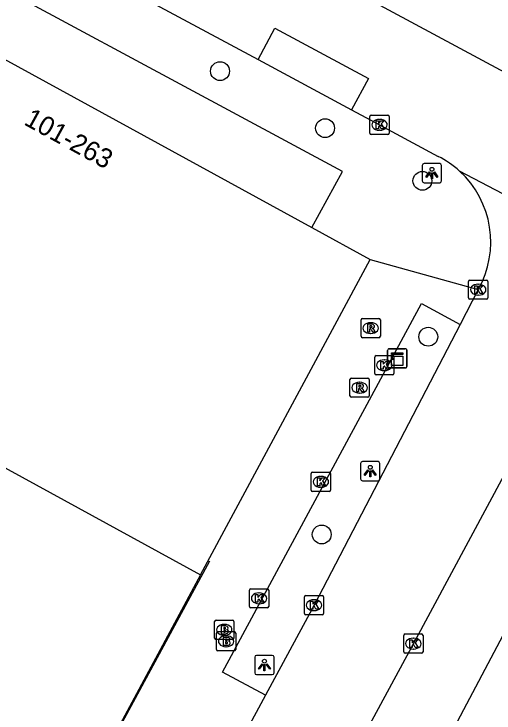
# Model space of a CAD drawing. Extents: x 159489 to 160304, y 383826 to 384530.
# Drawn here: x 159630.6 to 159655.5, y 384218.51 to 384254.79 of the extents above; entities that cross this region are included whole.
import ezdxf

# ---------------------------------------------------------------- set-up
doc = ezdxf.new("R2010")
doc.units = 0
for name, color, linetype in [('IMGEO_Boom', 7, 'Continuous'), ('IMGEO_Brandkraan', 7, 'Continuous'), ('IMGEO_Kast', 7, 'Continuous'), ('IMGEO_Kolk', 7, 'Continuous'), ('IMGEO_Lichtpunt', 7, 'Continuous'), ('IMGEO_Lijnafwatering', 7, 'Continuous'), ('IMGEO_Pand', 7, 'Continuous'), ('IMGEO_Pand_nummerreeks', 7, 'Continuous'), ('IMGEO_Pand_overbouw', 7, 'Continuous'), ('IMGEO_Rijbaan_lokaal_gesloten', 7, 'Continuous'), ('IMGEO_Rioolput', 7, 'Continuous'), ('IMGEO_Voetpad_open', 7, 'Continuous')]:
    doc.layers.add(name, color=color, linetype=linetype)

msp = doc.modelspace()

# ---------------------------------------------------------------- linework, layer by layer
at = {"layer": 'IMGEO_Boom'}
for centre in [(159641.29, 384251.824), (159646.74, 384248.864), (159651.788, 384246.131), (159652.093, 384238.04), (159646.565, 384227.78)]:
    msp.add_circle(centre, 0.489, dxfattribs=at)
at = {"layer": 'IMGEO_Brandkraan'}
for p, q in [((159641.085, 384223.33), (159641.937, 384223.33)), ((159641.01, 384222.404), (159641.01, 384223.256)), ((159641.498, 384223.11), (159641.523, 384223.11)), ((159642.011, 384223.256), (159642.011, 384222.404)), ((159641.105, 384221.81), (159641.105, 384222.662)), ((159641.18, 384222.736), (159642.032, 384222.736)), ((159642.106, 384222.662), (159642.106, 384221.81)), ((159641.937, 384222.33), (159641.085, 384222.33)), ((159641.521, 384222.55), (159641.496, 384222.55)), ((159641.593, 384222.516), (159641.618, 384222.516)), ((159641.616, 384221.956), (159641.591, 384221.956)), ((159642.032, 384221.736), (159641.18, 384221.736))]:
    msp.add_line(p, q, dxfattribs=at)
for points in [[(159641.085, 384223.33), (159641.937, 384223.33)], [(159641.01, 384222.404), (159641.01, 384223.256)], [(159641.358, 384223.03), (159641.358, 384222.63), (159641.571, 384222.63)], [(159641.589, 384223.03), (159641.358, 384223.03)], [(159641.537, 384222.949), (159641.483, 384222.949), (159641.483, 384222.873)], [(159642.011, 384223.256), (159642.011, 384222.404)], [(159641.105, 384221.81), (159641.105, 384222.662)], [(159641.18, 384222.736), (159642.032, 384222.736)], [(159641.483, 384222.873), (159641.536, 384222.873)], [(159641.545, 384222.797), (159641.483, 384222.797), (159641.483, 384222.716)], [(159641.483, 384222.716), (159641.545, 384222.716)], [(159642.106, 384222.662), (159642.106, 384221.81)], [(159641.937, 384222.33), (159641.085, 384222.33)], [(159641.453, 384222.436), (159641.453, 384222.036), (159641.666, 384222.036)], [(159641.684, 384222.436), (159641.453, 384222.436)], [(159641.632, 384222.355), (159641.578, 384222.355), (159641.578, 384222.279)], [(159641.578, 384222.279), (159641.631, 384222.279)], [(159641.64, 384222.203), (159641.578, 384222.203), (159641.578, 384222.122)], [(159641.578, 384222.122), (159641.64, 384222.122)], [(159642.032, 384221.736), (159641.18, 384221.736)]]:
    msp.add_lwpolyline(points, dxfattribs=at)
for centre, radius, start, end in [((159641.087, 384223.254), 0.0765, 91.552, 178.448), ((159641.087, 384223.254), 0.0765, 91.552, 178.448), ((159641.935, 384223.254), 0.0765, 1.552, 88.448), ((159641.935, 384223.254), 0.0765, 1.552, 88.448), ((159641.538, 384222.911), 0.0379, 267.8285, 90.9355), ((159641.593, 384222.885), 0.145, 59.4692, 91.5367), ((159641.618, 384222.932), 0.0922, 285.5137, 58.1501), ((159641.182, 384222.66), 0.0765, 91.552, 178.448), ((159641.182, 384222.66), 0.0765, 91.552, 178.448), ((159641.546, 384222.756), 0.0404, 269.8759, 90.5077), ((159641.577, 384222.881), 0.251, 268.6676, 293.5347), ((159641.623, 384222.74), 0.105, 301.3115, 78.989), ((159642.03, 384222.66), 0.0765, 1.552, 88.448), ((159642.03, 384222.66), 0.0765, 1.552, 88.448), ((159641.087, 384222.406), 0.0765, 181.552, 268.448), ((159641.087, 384222.406), 0.0765, 181.552, 268.448), ((159641.633, 384222.317), 0.0379, 267.8285, 90.9355), ((159641.641, 384222.162), 0.0404, 269.8759, 90.5077), ((159641.688, 384222.291), 0.145, 59.4692, 91.5367), ((159641.713, 384222.338), 0.0922, 285.5137, 58.1501), ((159641.718, 384222.146), 0.105, 301.3115, 78.989), ((159641.935, 384222.406), 0.0765, 271.552, 358.448), ((159641.935, 384222.406), 0.0765, 271.552, 358.448), ((159641.672, 384222.287), 0.251, 268.6676, 293.5347), ((159641.182, 384221.812), 0.0765, 181.552, 268.448), ((159641.182, 384221.812), 0.0765, 181.552, 268.448), ((159642.03, 384221.812), 0.0765, 271.552, 358.448), ((159642.03, 384221.812), 0.0765, 271.552, 358.448)]:
    msp.add_arc(centre, radius, start, end, dxfattribs=at)
for centre, major_axis, ratio, start_param, end_param in [((159641.497, 384222.83), (-0.387, 0.002), 0.722429, 4.712389, 7.853982), ((159641.522, 384222.83), (-0.39, 0.002), 0.717154, 1.570796, 4.712389), ((159641.592, 384222.236), (-0.387, 0.002), 0.722429, 4.712389, 7.853982), ((159641.617, 384222.236), (-0.39, 0.002), 0.717154, 1.570796, 4.712389)]:
    msp.add_ellipse(centre, major_axis=major_axis, ratio=ratio, start_param=start_param, end_param=end_param, dxfattribs=at)
at = {"layer": 'IMGEO_Kast'}
for p, q in [((159649.985, 384236.494), (159649.985, 384237.335)), ((159649.985, 384237.335), (159649.985, 384236.494)), ((159650.06, 384237.419), (159650.901, 384237.419)), ((159650.901, 384237.419), (159650.06, 384237.419)), ((159650.985, 384237.344), (159650.985, 384236.503)), ((159650.985, 384236.503), (159650.985, 384237.344)), ((159650.91, 384236.419), (159650.069, 384236.419)), ((159650.069, 384236.419), (159650.91, 384236.419))]:
    msp.add_line(p, q, dxfattribs=at)
for points in [[(159650.18, 384237.209), (159650.78, 384237.209), (159650.78, 384237.124), (159650.18, 384237.124), (159650.18, 384237.209)], [(159650.18, 384237.034), (159650.78, 384237.034), (159650.78, 384236.545), (159650.18, 384236.545), (159650.18, 384237.034)]]:
    msp.add_lwpolyline(points, dxfattribs=at)
msp.add_circle((159650.264, 384236.883), 0.0377, dxfattribs=at)
for centre, start, end in [((159650.063, 384237.341), 92.4484, 184.2845), ((159650.063, 384237.341), 92.4484, 184.2845), ((159650.907, 384237.341), 2.4484, 94.2845), ((159650.907, 384237.341), 2.4484, 94.2845), ((159650.063, 384236.497), 182.4484, 274.2845), ((159650.063, 384236.497), 182.4484, 274.2845), ((159650.907, 384236.497), 272.4484, 4.2845), ((159650.907, 384236.497), 272.4484, 4.2845)]:
    msp.add_arc(centre, 0.0779, start, end, dxfattribs=at)
at = {"layer": 'IMGEO_Kolk'}
for p, q in [((159649.064, 384248.611), (159649.064, 384249.463)), ((159649.139, 384249.537), (159649.991, 384249.537)), ((159650.065, 384249.463), (159650.065, 384248.611)), ((159649.552, 384249.317), (159649.577, 384249.317)), ((159649.575, 384248.757), (159649.55, 384248.757)), ((159649.991, 384248.537), (159649.139, 384248.537)), ((159654.183, 384240.058), (159654.183, 384240.91)), ((159654.258, 384240.984), (159655.11, 384240.984)), ((159654.671, 384240.764), (159654.696, 384240.764)), ((159655.184, 384240.91), (159655.184, 384240.058)), ((159655.11, 384239.984), (159654.258, 384239.984)), ((159654.694, 384240.204), (159654.669, 384240.204)), ((159649.313, 384236.135), (159649.313, 384236.987)), ((159649.388, 384237.061), (159650.24, 384237.061)), ((159649.801, 384236.841), (159649.826, 384236.841)), ((159650.314, 384236.987), (159650.314, 384236.135)), ((159650.24, 384236.061), (159649.388, 384236.061)), ((159649.824, 384236.281), (159649.799, 384236.281)), ((159646.021, 384230.086), (159646.021, 384230.938)), ((159646.096, 384231.012), (159646.948, 384231.012)), ((159647.022, 384230.938), (159647.022, 384230.086)), ((159646.509, 384230.792), (159646.534, 384230.792)), ((159646.532, 384230.232), (159646.507, 384230.232)), ((159646.948, 384230.012), (159646.096, 384230.012)), ((159642.816, 384224.039), (159642.816, 384224.891)), ((159642.891, 384224.965), (159643.743, 384224.965)), ((159643.304, 384224.745), (159643.329, 384224.745)), ((159643.817, 384224.891), (159643.817, 384224.039)), ((159645.665, 384223.684), (159645.665, 384224.536)), ((159645.74, 384224.61), (159646.592, 384224.61)), ((159646.153, 384224.39), (159646.178, 384224.39)), ((159646.666, 384224.536), (159646.666, 384223.684)), ((159643.327, 384224.185), (159643.302, 384224.185)), ((159643.743, 384223.965), (159642.891, 384223.965)), ((159646.176, 384223.83), (159646.151, 384223.83)), ((159646.592, 384223.61), (159645.74, 384223.61)), ((159650.895, 384222.615), (159651.747, 384222.615)), ((159650.82, 384221.689), (159650.82, 384222.541)), ((159651.308, 384222.395), (159651.333, 384222.395)), ((159651.821, 384222.541), (159651.821, 384221.689)), ((159651.747, 384221.615), (159650.895, 384221.615)), ((159651.331, 384221.835), (159651.306, 384221.835))]:
    msp.add_line(p, q, dxfattribs=at)
for points in [[(159649.064, 384248.611), (159649.064, 384249.463)], [(159649.139, 384249.537), (159649.991, 384249.537)], [(159650.065, 384249.463), (159650.065, 384248.611)], [(159649.385, 384249.237), (159649.508, 384249.237), (159649.508, 384249.086), (159649.638, 384249.237), (159649.802, 384249.237), (159649.656, 384249.086), (159649.809, 384248.837), (159649.657, 384248.837), (159649.572, 384249.001), (159649.508, 384248.934), (159649.508, 384248.837), (159649.385, 384248.837), (159649.385, 384249.237)], [(159649.991, 384248.537), (159649.139, 384248.537)], [(159654.183, 384240.058), (159654.183, 384240.91)], [(159654.258, 384240.984), (159655.11, 384240.984)], [(159655.184, 384240.91), (159655.184, 384240.058)], [(159654.504, 384240.684), (159654.627, 384240.684), (159654.627, 384240.533), (159654.757, 384240.684), (159654.921, 384240.684), (159654.775, 384240.533), (159654.928, 384240.284), (159654.776, 384240.284), (159654.691, 384240.448), (159654.627, 384240.381), (159654.627, 384240.284), (159654.504, 384240.284), (159654.504, 384240.684)], [(159655.11, 384239.984), (159654.258, 384239.984)], [(159649.313, 384236.135), (159649.313, 384236.987)], [(159649.388, 384237.061), (159650.24, 384237.061)], [(159649.634, 384236.761), (159649.757, 384236.761), (159649.757, 384236.61), (159649.887, 384236.761), (159650.051, 384236.761), (159649.905, 384236.61), (159650.058, 384236.361), (159649.906, 384236.361), (159649.821, 384236.525), (159649.757, 384236.458), (159649.757, 384236.361), (159649.634, 384236.361), (159649.634, 384236.761)], [(159650.314, 384236.987), (159650.314, 384236.135)], [(159650.24, 384236.061), (159649.388, 384236.061)], [(159646.021, 384230.086), (159646.021, 384230.938)], [(159646.096, 384231.012), (159646.948, 384231.012)], [(159647.022, 384230.938), (159647.022, 384230.086)], [(159646.342, 384230.712), (159646.465, 384230.712), (159646.465, 384230.561), (159646.595, 384230.712), (159646.759, 384230.712), (159646.613, 384230.561), (159646.766, 384230.312), (159646.614, 384230.312), (159646.529, 384230.476), (159646.465, 384230.409), (159646.465, 384230.312), (159646.342, 384230.312), (159646.342, 384230.712)], [(159646.948, 384230.012), (159646.096, 384230.012)], [(159642.816, 384224.039), (159642.816, 384224.891)], [(159642.891, 384224.965), (159643.743, 384224.965)], [(159643.817, 384224.891), (159643.817, 384224.039)], [(159643.137, 384224.665), (159643.26, 384224.665), (159643.26, 384224.514), (159643.39, 384224.665), (159643.554, 384224.665), (159643.408, 384224.514), (159643.561, 384224.265), (159643.409, 384224.265), (159643.324, 384224.429), (159643.26, 384224.362), (159643.26, 384224.265), (159643.137, 384224.265), (159643.137, 384224.665)], [(159645.665, 384223.684), (159645.665, 384224.536)], [(159645.74, 384224.61), (159646.592, 384224.61)], [(159646.666, 384224.536), (159646.666, 384223.684)], [(159645.986, 384224.31), (159646.109, 384224.31), (159646.109, 384224.159), (159646.239, 384224.31), (159646.403, 384224.31), (159646.257, 384224.159), (159646.41, 384223.91), (159646.258, 384223.91), (159646.173, 384224.074), (159646.109, 384224.007), (159646.109, 384223.91), (159645.986, 384223.91), (159645.986, 384224.31)], [(159643.743, 384223.965), (159642.891, 384223.965)], [(159646.592, 384223.61), (159645.74, 384223.61)], [(159650.895, 384222.615), (159651.747, 384222.615)], [(159650.82, 384221.689), (159650.82, 384222.541)], [(159651.141, 384222.315), (159651.264, 384222.315), (159651.264, 384222.164), (159651.394, 384222.315), (159651.558, 384222.315), (159651.412, 384222.164), (159651.565, 384221.915), (159651.413, 384221.915), (159651.328, 384222.079), (159651.264, 384222.012), (159651.264, 384221.915), (159651.141, 384221.915), (159651.141, 384222.315)], [(159651.821, 384222.541), (159651.821, 384221.689)], [(159651.747, 384221.615), (159650.895, 384221.615)]]:
    msp.add_lwpolyline(points, dxfattribs=at)
for centre, start, end in [((159649.141, 384249.461), 91.552, 178.448), ((159649.141, 384249.461), 91.552, 178.448), ((159649.989, 384249.461), 1.552, 88.448), ((159649.989, 384249.461), 1.552, 88.448), ((159649.141, 384248.613), 181.552, 268.448), ((159649.141, 384248.613), 181.552, 268.448), ((159649.989, 384248.613), 271.552, 358.448), ((159649.989, 384248.613), 271.552, 358.448), ((159654.26, 384240.908), 91.552, 178.448), ((159654.26, 384240.908), 91.552, 178.448), ((159655.108, 384240.908), 1.552, 88.448), ((159655.108, 384240.908), 1.552, 88.448), ((159654.26, 384240.06), 181.552, 268.448), ((159654.26, 384240.06), 181.552, 268.448), ((159655.108, 384240.06), 271.552, 358.448), ((159655.108, 384240.06), 271.552, 358.448), ((159649.39, 384236.985), 91.552, 178.448), ((159649.39, 384236.985), 91.552, 178.448), ((159650.238, 384236.985), 1.552, 88.448), ((159650.238, 384236.985), 1.552, 88.448), ((159649.39, 384236.137), 181.552, 268.448), ((159649.39, 384236.137), 181.552, 268.448), ((159650.238, 384236.137), 271.552, 358.448), ((159650.238, 384236.137), 271.552, 358.448), ((159646.098, 384230.936), 91.552, 178.448), ((159646.098, 384230.936), 91.552, 178.448), ((159646.946, 384230.936), 1.552, 88.448), ((159646.946, 384230.936), 1.552, 88.448), ((159646.098, 384230.088), 181.552, 268.448), ((159646.098, 384230.088), 181.552, 268.448), ((159646.946, 384230.088), 271.552, 358.448), ((159646.946, 384230.088), 271.552, 358.448), ((159642.893, 384224.889), 91.552, 178.448), ((159642.893, 384224.889), 91.552, 178.448), ((159643.741, 384224.889), 1.552, 88.448), ((159643.741, 384224.889), 1.552, 88.448), ((159645.742, 384224.534), 91.552, 178.448), ((159645.742, 384224.534), 91.552, 178.448), ((159646.59, 384224.534), 1.552, 88.448), ((159646.59, 384224.534), 1.552, 88.448), ((159642.893, 384224.041), 181.552, 268.448), ((159642.893, 384224.041), 181.552, 268.448), ((159643.741, 384224.041), 271.552, 358.448), ((159643.741, 384224.041), 271.552, 358.448), ((159645.742, 384223.686), 181.552, 268.448), ((159645.742, 384223.686), 181.552, 268.448), ((159646.59, 384223.686), 271.552, 358.448), ((159646.59, 384223.686), 271.552, 358.448), ((159650.897, 384222.539), 91.552, 178.448), ((159650.897, 384222.539), 91.552, 178.448), ((159651.745, 384222.539), 1.552, 88.448), ((159651.745, 384222.539), 1.552, 88.448), ((159650.897, 384221.691), 181.552, 268.448), ((159650.897, 384221.691), 181.552, 268.448), ((159651.745, 384221.691), 271.552, 358.448), ((159651.745, 384221.691), 271.552, 358.448)]:
    msp.add_arc(centre, 0.0765, start, end, dxfattribs=at)
for centre, major_axis, ratio, start_param, end_param in [((159649.551, 384249.037), (-0.387, 0.002), 0.722429, 4.712389, 7.853982), ((159649.576, 384249.037), (-0.39, 0.002), 0.717154, 1.570796, 4.712389), ((159654.67, 384240.484), (-0.387, 0.002), 0.722429, 4.712389, 7.853982), ((159654.695, 384240.484), (-0.39, 0.002), 0.717154, 1.570796, 4.712389), ((159649.8, 384236.561), (-0.387, 0.002), 0.722429, 4.712389, 7.853982), ((159649.825, 384236.561), (-0.39, 0.002), 0.717154, 1.570796, 4.712389), ((159646.508, 384230.512), (-0.387, 0.002), 0.722429, 4.712389, 7.853982), ((159646.533, 384230.512), (-0.39, 0.002), 0.717154, 1.570796, 4.712389), ((159643.303, 384224.465), (-0.387, 0.002), 0.722429, 4.712389, 7.853982), ((159643.328, 384224.465), (-0.39, 0.002), 0.717154, 1.570796, 4.712389), ((159646.152, 384224.11), (-0.387, 0.002), 0.722429, 4.712389, 7.853982), ((159646.177, 384224.11), (-0.39, 0.002), 0.717154, 1.570796, 4.712389), ((159651.307, 384222.115), (-0.387, 0.002), 0.722429, 4.712389, 7.853982), ((159651.332, 384222.115), (-0.39, 0.002), 0.717154, 1.570796, 4.712389)]:
    msp.add_ellipse(centre, major_axis=major_axis, ratio=ratio, start_param=start_param, end_param=end_param, dxfattribs=at)
at = {"layer": 'IMGEO_Lichtpunt'}
for p, q in [((159651.784, 384246.933), (159651.784, 384246.126)), ((159651.784, 384246.933), (159651.784, 384246.126)), ((159652.686, 384247.028), (159651.878, 384247.028)), ((159652.686, 384247.028), (159651.878, 384247.028)), ((159652.78, 384246.126), (159652.78, 384246.933)), ((159652.78, 384246.126), (159652.78, 384246.933)), ((159651.878, 384246.032), (159652.686, 384246.032)), ((159651.878, 384246.032), (159652.686, 384246.032)), ((159648.585, 384231.469), (159648.585, 384230.662)), ((159648.585, 384231.469), (159648.585, 384230.662)), ((159649.487, 384231.564), (159648.679, 384231.564)), ((159649.487, 384231.564), (159648.679, 384231.564)), ((159649.581, 384230.662), (159649.581, 384231.469)), ((159649.581, 384230.662), (159649.581, 384231.469)), ((159648.679, 384230.568), (159649.487, 384230.568)), ((159648.679, 384230.568), (159649.487, 384230.568)), ((159643.997, 384221.505), (159643.189, 384221.505)), ((159643.997, 384221.505), (159643.189, 384221.505)), ((159643.095, 384221.41), (159643.095, 384220.603)), ((159643.095, 384221.41), (159643.095, 384220.603)), ((159644.091, 384220.603), (159644.091, 384221.41)), ((159644.091, 384220.603), (159644.091, 384221.41)), ((159643.189, 384220.509), (159643.997, 384220.509)), ((159643.189, 384220.509), (159643.997, 384220.509))]:
    msp.add_line(p, q, dxfattribs=at)
for points in [[(159652.158, 384246.597), (159652.197, 384246.569), (159652.009, 384246.307), (159651.971, 384246.334), (159652.158, 384246.597)], [(159652.26, 384246.549), (159652.307, 384246.549), (159652.307, 384246.227), (159652.26, 384246.227), (159652.26, 384246.549)], [(159652.37, 384246.569), (159652.408, 384246.596), (159652.595, 384246.334), (159652.556, 384246.306), (159652.37, 384246.569)], [(159648.959, 384231.133), (159648.998, 384231.105), (159648.81, 384230.843), (159648.772, 384230.87), (159648.959, 384231.133)], [(159649.061, 384231.085), (159649.108, 384231.085), (159649.108, 384230.763), (159649.061, 384230.763), (159649.061, 384231.085)], [(159649.171, 384231.105), (159649.209, 384231.132), (159649.396, 384230.87), (159649.357, 384230.842), (159649.171, 384231.105)], [(159643.469, 384221.074), (159643.508, 384221.046), (159643.32, 384220.784), (159643.282, 384220.811), (159643.469, 384221.074)], [(159643.571, 384221.026), (159643.618, 384221.026), (159643.618, 384220.704), (159643.571, 384220.704), (159643.571, 384221.026)], [(159643.681, 384221.046), (159643.719, 384221.073), (159643.906, 384220.811), (159643.867, 384220.783), (159643.681, 384221.046)]]:
    msp.add_lwpolyline(points, dxfattribs=at)
for centre in [(159652.283, 384246.731), (159649.084, 384231.267), (159643.594, 384221.208)]:
    msp.add_circle(centre, 0.0994, dxfattribs=at)
for centre, start, end in [((159651.878, 384246.933), 90, 180), ((159651.878, 384246.933), 90, 180), ((159652.686, 384246.933), 0, 90), ((159652.686, 384246.933), 0, 90), ((159651.878, 384246.126), 180, 270), ((159651.878, 384246.126), 180, 270), ((159652.686, 384246.126), 270, 0), ((159652.686, 384246.126), 270, 360), ((159648.679, 384231.469), 90, 180), ((159648.679, 384231.469), 90, 180), ((159649.487, 384231.469), 0, 90), ((159649.487, 384231.469), 0, 90), ((159648.679, 384230.662), 180, 270), ((159648.679, 384230.662), 180, 270), ((159649.487, 384230.662), 270, 0), ((159649.487, 384230.662), 270, 360), ((159643.189, 384221.41), 90, 180), ((159643.189, 384221.41), 90, 180), ((159643.997, 384221.41), 0, 90), ((159643.997, 384221.41), 0, 90), ((159643.189, 384220.603), 180, 270), ((159643.189, 384220.603), 180, 270), ((159643.997, 384220.603), 270, 0), ((159643.997, 384220.603), 270, 360)]:
    msp.add_arc(centre, 0.0946, start, end, dxfattribs=at)
at = {"layer": 'IMGEO_Lijnafwatering'}
msp.add_lwpolyline([(159633.971, 384213.85), (159640.759, 384226.414)], dxfattribs=at)
at = {"layer": 'IMGEO_Pand'}
for points in [[(159620.712, 384257.605), (159621.017, 384257.441), (159621.346, 384257.26), (159646.05, 384243.709), (159649.079, 384242.048)], [(159616.379, 384249.69), (159611.777, 384241.285), (159640.276, 384225.681)], [(159640.276, 384225.681), (159649.079, 384242.048)], [(159651.4, 384213.888), (159662.333, 384234.555)]]:
    msp.add_lwpolyline(points, dxfattribs=at)
at = {"layer": 'IMGEO_Pand_overbouw'}
msp.add_lwpolyline([(159621.346, 384257.26), (159646.05, 384243.709), (159647.644, 384246.614), (159622.814, 384259.985)], close=True, dxfattribs=at)
at = {"layer": 'IMGEO_Rijbaan_lokaal_gesloten'}
for points in [[(159643.082, 384258.763), (159687.782, 384234.713)], [(159633.545, 384257.652), (159643.266, 384252.424)], [(159643.266, 384252.424), (159644.14, 384254.05), (159648.99, 384251.442), (159648.115, 384249.816)], [(159648.115, 384249.816), (159649.108, 384249.282), (159652.612, 384247.398)], [(159666.397, 384239.997), (159653.711, 384246.637)], [(159654.684, 384240.484), (159653.747, 384238.682)], [(159653.747, 384238.682), (159646.166, 384224.11), (159643.655, 384219.446)], [(159658.978, 384236.342), (159651.321, 384222.115), (159647.908, 384215.784)], [(159643.655, 384219.446), (159639.366, 384211.481)]]:
    msp.add_lwpolyline(points, dxfattribs=at)
for centre, radius, start, end in [((159650.318, 384242.911), 5.039, 47.677, 62.9218), ((159650.343, 384242.951), 4.993, 330.3891, 47.5829)]:
    msp.add_arc(centre, radius, start, end, dxfattribs=at)
at = {"layer": 'IMGEO_Rioolput'}
for p, q in [((159648.606, 384238.063), (159648.606, 384238.915)), ((159648.681, 384238.989), (159649.533, 384238.989)), ((159649.607, 384238.915), (159649.607, 384238.063)), ((159649.094, 384238.769), (159649.119, 384238.769)), ((159649.117, 384238.209), (159649.092, 384238.209)), ((159649.533, 384237.989), (159648.681, 384237.989)), ((159648.032, 384234.971), (159648.032, 384235.823)), ((159648.107, 384235.897), (159648.959, 384235.897)), ((159648.52, 384235.677), (159648.545, 384235.677)), ((159649.033, 384235.823), (159649.033, 384234.971)), ((159648.959, 384234.897), (159648.107, 384234.897)), ((159648.543, 384235.117), (159648.518, 384235.117))]:
    msp.add_line(p, q, dxfattribs=at)
for points in [[(159648.606, 384238.063), (159648.606, 384238.915)], [(159648.681, 384238.989), (159649.533, 384238.989)], [(159649.607, 384238.915), (159649.607, 384238.063)], [(159649.195, 384238.687), (159648.943, 384238.689), (159648.943, 384238.289)], [(159649.121, 384238.608), (159649.067, 384238.608), (159649.067, 384238.527)], [(159649.067, 384238.527), (159649.119, 384238.527)], [(159648.943, 384238.289), (159649.067, 384238.289), (159649.067, 384238.451), (159649.078, 384238.451)], [(159649.125, 384238.422), (159649.196, 384238.289), (159649.336, 384238.289), (159649.271, 384238.415)], [(159649.533, 384237.989), (159648.681, 384237.989)], [(159648.032, 384234.971), (159648.032, 384235.823)], [(159648.107, 384235.897), (159648.959, 384235.897)], [(159649.033, 384235.823), (159649.033, 384234.971)], [(159648.621, 384235.595), (159648.369, 384235.597), (159648.369, 384235.197)], [(159648.369, 384235.197), (159648.493, 384235.197), (159648.493, 384235.359), (159648.504, 384235.359)], [(159648.547, 384235.516), (159648.493, 384235.516), (159648.493, 384235.435)], [(159648.493, 384235.435), (159648.545, 384235.435)], [(159648.551, 384235.33), (159648.622, 384235.197), (159648.762, 384235.197), (159648.697, 384235.323)], [(159648.959, 384234.897), (159648.107, 384234.897)]]:
    msp.add_lwpolyline(points, dxfattribs=at)
for centre, radius, start, end in [((159648.683, 384238.913), 0.0765, 91.552, 178.448), ((159648.683, 384238.913), 0.0765, 91.552, 178.448), ((159649.531, 384238.913), 0.0765, 1.552, 88.448), ((159649.531, 384238.913), 0.0765, 1.552, 88.448), ((159649.103, 384238.716), 0.19, 274.7715, 282.9687), ((159649.127, 384238.512), 0.0964, 77.0061, 93.1865), ((159649.141, 384238.569), 0.0378, 276.6634, 79.6772), ((159649.194, 384238.577), 0.109, 350.3612, 89.416), ((159649.192, 384238.577), 0.112, 277.5842, 350.9817), ((159649.077, 384238.398), 0.0533, 26.0293, 88.6989), ((159649.176, 384238.362), 0.108, 29.5134, 73.7905), ((159648.683, 384238.065), 0.0765, 181.552, 268.448), ((159648.683, 384238.065), 0.0765, 181.552, 268.448), ((159649.531, 384238.065), 0.0765, 271.552, 358.448), ((159649.531, 384238.065), 0.0765, 271.552, 358.448), ((159648.109, 384235.821), 0.0765, 91.552, 178.448), ((159648.109, 384235.821), 0.0765, 91.552, 178.448), ((159648.957, 384235.821), 0.0765, 1.552, 88.448), ((159648.957, 384235.821), 0.0765, 1.552, 88.448), ((159648.503, 384235.306), 0.0533, 26.0293, 88.6989), ((159648.529, 384235.624), 0.19, 274.7715, 282.9687), ((159648.553, 384235.42), 0.0964, 77.0061, 93.1865), ((159648.567, 384235.477), 0.0378, 276.6634, 79.6772), ((159648.62, 384235.485), 0.109, 350.3612, 89.416), ((159648.618, 384235.485), 0.112, 277.5842, 350.9817), ((159648.602, 384235.27), 0.108, 29.5134, 73.7905), ((159648.109, 384234.973), 0.0765, 181.552, 268.448), ((159648.109, 384234.973), 0.0765, 181.552, 268.448), ((159648.957, 384234.973), 0.0765, 271.552, 358.448), ((159648.957, 384234.973), 0.0765, 271.552, 358.448)]:
    msp.add_arc(centre, radius, start, end, dxfattribs=at)
for centre, major_axis, ratio, start_param, end_param in [((159649.093, 384238.489), (-0.387, 0.002), 0.722429, 4.712389, 7.853982), ((159649.118, 384238.489), (-0.39, 0.002), 0.717154, 1.570796, 4.712389), ((159648.519, 384235.397), (-0.387, 0.002), 0.722429, 4.712389, 7.853982), ((159648.544, 384235.397), (-0.39, 0.002), 0.717154, 1.570796, 4.712389)]:
    msp.add_ellipse(centre, major_axis=major_axis, ratio=ratio, start_param=start_param, end_param=end_param, dxfattribs=at)
at = {"layer": 'IMGEO_Voetpad_open'}
for points in [[(159643.266, 384252.424), (159648.115, 384249.816)], [(159649.079, 384242.048), (159654.684, 384240.484)], [(159643.655, 384219.446), (159641.422, 384220.631), (159651.736, 384239.768), (159653.747, 384238.682)], [(159640.276, 384225.681), (159631.56, 384209.476), (159627.071, 384201.275)]]:
    msp.add_lwpolyline(points, dxfattribs=at)

# ---------------------------------------------------------------- texts
at = {"layer": 'IMGEO_Pand_nummerreeks'}
msp.add_text('101-263', height=1, rotation=331.2432, dxfattribs=at).set_placement((159631.067, 384249.077))

doc.saveas('drawing.dxf')
